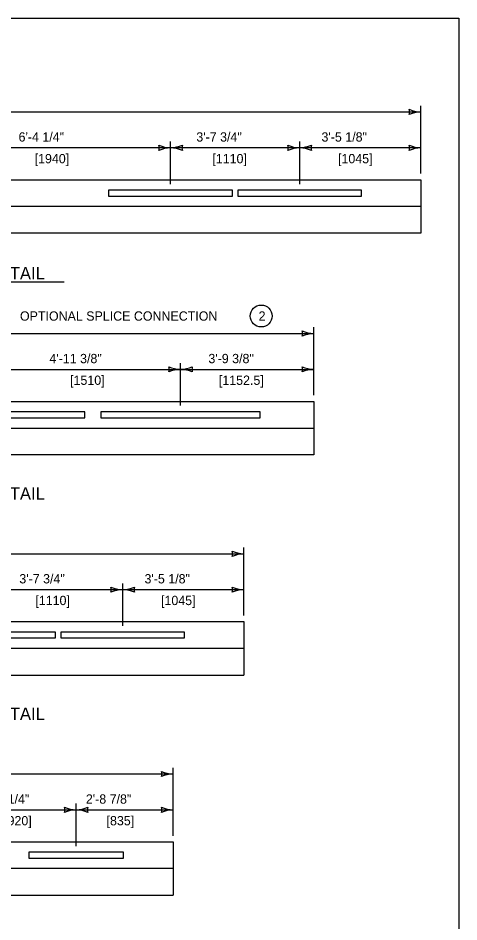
# Model space of a CAD drawing. Extents: x 49991.4 to 50021, y 49987.6 to 50011.4.
# Drawn here: x 50013.9 to 50016.75, y 49993.16 to 49999 of the extents above; entities that cross this region are included whole.
import ezdxf

# ---------------------------------------------------------------- set-up
doc = ezdxf.new("R2010")
doc.units = 0
for name, color, linetype in [('Level 1', 7, 'Continuous'), ('Level 2', 7, 'Continuous'), ('Level 3', 7, 'Continuous'), ('Level 5', 7, 'Continuous')]:
    doc.layers.add(name, color=color, linetype=linetype)

msp = doc.modelspace()

# ---------------------------------------------------------------- linework, layer by layer
at = {"layer": 'Level 1'}
for p, q in [((50009.5326, 49997.9545), (50016.5051, 49997.9545)), ((50016.5051, 49997.9545), (50016.5051, 49997.6095)), ((50015.2883, 49997.8874), (50014.4882, 49997.8874)), ((50014.4882, 49997.8874), (50014.4882, 49997.8491)), ((50014.4882, 49997.8491), (50015.2883, 49997.8491)), ((50015.2883, 49997.8491), (50015.2883, 49997.8874)), ((50016.1217, 49997.8874), (50015.3216, 49997.8874)), ((50015.3216, 49997.8874), (50015.3216, 49997.8491)), ((50015.3216, 49997.8491), (50016.1217, 49997.8491)), ((50016.1217, 49997.8491), (50016.1217, 49997.8874)), ((50016.5051, 49997.782), (50013.0188, 49997.782)), ((50016.5051, 49997.6095), (50009.5326, 49997.6095)), ((50010.2124, 49996.5232), (50015.8133, 49996.5232)), ((50015.8133, 49996.5232), (50015.8133, 49996.1782)), ((50014.3336, 49996.4561), (50013.3061, 49996.4561)), ((50014.3336, 49996.4178), (50014.3336, 49996.4561)), ((50015.4661, 49996.4561), (50014.4386, 49996.4561)), ((50014.4386, 49996.4561), (50014.4386, 49996.4178)), ((50015.4661, 49996.4178), (50015.4661, 49996.4561)), ((50013.3061, 49996.4178), (50014.3336, 49996.4178)), ((50014.4386, 49996.4178), (50015.4661, 49996.4178)), ((50010.2124, 49996.3507), (50015.8133, 49996.3507)), ((50015.8133, 49996.1782), (50010.2124, 49996.1782)), ((50010.6756, 49995.1007), (50015.3621, 49995.1007)), ((50015.3621, 49995.1007), (50015.3621, 49994.7557)), ((50014.1453, 49995.0336), (50013.3452, 49995.0336)), ((50013.3452, 49994.9953), (50014.1453, 49994.9953)), ((50014.1453, 49994.9953), (50014.1453, 49995.0336)), ((50014.9787, 49995.0336), (50014.1786, 49995.0336)), ((50014.1786, 49995.0336), (50014.1786, 49994.9953)), ((50014.1786, 49994.9953), (50014.9787, 49994.9953)), ((50014.9787, 49994.9953), (50014.9787, 49995.0336)), ((50015.3621, 49994.9282), (50010.6756, 49994.9282)), ((50010.6756, 49994.7557), (50015.3621, 49994.7557)), ((50011.1328, 49993.6782), (50014.9049, 49993.6782)), ((50014.9049, 49993.6782), (50014.9049, 49993.3332)), ((50014.5834, 49993.611), (50013.9738, 49993.611)), ((50013.9738, 49993.611), (50013.9738, 49993.5729)), ((50014.5834, 49993.5729), (50014.5834, 49993.611)), ((50013.9738, 49993.5729), (50014.5834, 49993.5729)), ((50014.9049, 49993.5057), (50011.1328, 49993.5057)), ((50011.1328, 49993.3332), (50014.9049, 49993.3332))]:
    msp.add_line(p, q, dxfattribs=at)
msp.add_lwpolyline([(49999.3835, 49998.9992), (50016.7501, 49998.9992), (50016.7501, 49987.7988), (49999.3835, 49987.7988)], close=True, dxfattribs=at)
at = {"layer": 'Level 2'}
msp.add_line((50011.8387, 49997.2947), (50014.2011, 49997.2947), dxfattribs=at)
msp.add_circle((50015.4734, 49997.0747), 0.0707, dxfattribs=at)
at = {"layer": 'Level 3'}
for p, q in [((50016.5051, 49997.9945), (50016.5051, 49998.433)), ((50011.3412, 49998.393), (50016.5051, 49998.393)), ((50014.8882, 49998.1614), (50013.4262, 49998.1614)), ((50015.7217, 49998.1614), (50014.8882, 49998.1614)), ((50016.5051, 49998.1614), (50015.7217, 49998.1614)), ((50015.8133, 49996.5632), (50015.8133, 49997.0017)), ((50013.6885, 49996.9617), (50015.8133, 49996.9617)), ((50013.8199, 49996.7301), (50014.9524, 49996.7301)), ((50014.9524, 49996.7301), (50015.8133, 49996.7301)), ((50015.3621, 49995.1407), (50015.3621, 49995.5792)), ((50010.6756, 49995.5392), (50015.3621, 49995.5392)), ((50013.7452, 49995.3076), (50014.5787, 49995.3076)), ((50014.5787, 49995.3076), (50015.3621, 49995.3076)), ((50011.1328, 49994.1167), (50014.9049, 49994.1167)), ((50014.9049, 49993.7182), (50014.9049, 49994.1567)), ((50013.5875, 49993.885), (50014.2786, 49993.885)), ((50014.2786, 49993.885), (50014.9049, 49993.885))]:
    msp.add_line(p, q, dxfattribs=at)
for centre, radius, start, end in [((50016.5142, 49998.6151), 0.2223, 247.45601, 267.63952), ((50016.3768, 49998.393), 0.0548, 342.13882, 17.86118), ((50016.5166, 49998.1602), 0.233, 92.82731, 112.07716), ((50014.8974, 49998.3835), 0.2223, 247.45601, 267.63952), ((50014.76, 49998.1614), 0.0548, 342.13882, 17.86118), ((50014.8997, 49997.9287), 0.233, 92.82731, 112.07716), ((50014.8768, 49998.3941), 0.233, 272.82731, 292.07716), ((50014.8791, 49997.9393), 0.2223, 67.45601, 87.63952), ((50015.0165, 49998.1614), 0.0548, 162.13882, 197.86118), ((50015.7308, 49998.3835), 0.2223, 247.45601, 267.63952), ((50015.5934, 49998.1614), 0.0548, 342.13882, 17.86118), ((50015.7332, 49997.9287), 0.233, 92.82731, 112.07716), ((50015.7102, 49998.3941), 0.233, 272.82731, 292.07716), ((50015.7125, 49997.9393), 0.2223, 67.45601, 87.63952), ((50015.8499, 49998.1614), 0.0548, 162.13882, 197.86118), ((50016.5142, 49998.3835), 0.2223, 247.45601, 267.63952), ((50016.3768, 49998.1614), 0.0548, 342.13882, 17.86118), ((50016.5166, 49997.9287), 0.233, 92.82731, 112.07716), ((50015.8224, 49997.1838), 0.2223, 247.45601, 267.63952), ((50015.685, 49996.9617), 0.0548, 342.13882, 17.86118), ((50015.8248, 49996.7289), 0.233, 92.82731, 112.07716), ((50014.9615, 49996.9522), 0.2223, 247.45601, 267.63952), ((50014.8242, 49996.7301), 0.0548, 342.13882, 17.86118), ((50014.9639, 49996.4974), 0.233, 92.82731, 112.07716), ((50014.9409, 49996.9628), 0.233, 272.82731, 292.07716), ((50014.9432, 49996.508), 0.2223, 67.45601, 87.63952), ((50015.0806, 49996.7301), 0.0548, 162.13882, 197.86118), ((50015.8224, 49996.9522), 0.2223, 247.45601, 267.63952), ((50015.685, 49996.7301), 0.0548, 342.13882, 17.86118), ((50015.8248, 49996.4974), 0.233, 92.82731, 112.07716), ((50015.3712, 49995.7613), 0.2223, 247.45601, 267.63952), ((50015.2338, 49995.5392), 0.0548, 342.13882, 17.86118), ((50015.3736, 49995.3064), 0.233, 92.82731, 112.07716), ((50014.5878, 49995.5297), 0.2223, 247.45601, 267.63952), ((50014.4504, 49995.3076), 0.0548, 342.13882, 17.86118), ((50014.5902, 49995.0749), 0.233, 92.82731, 112.07716), ((50014.5672, 49995.5403), 0.233, 272.82731, 292.07716), ((50014.5695, 49995.0855), 0.2223, 67.45601, 87.63952), ((50014.7069, 49995.3076), 0.0548, 162.13882, 197.86118), ((50015.3712, 49995.5297), 0.2223, 247.45601, 267.63952), ((50015.2338, 49995.3076), 0.0548, 342.13882, 17.86118), ((50015.3736, 49995.0749), 0.233, 92.82731, 112.07716), ((50014.914, 49994.3388), 0.2223, 247.45601, 267.63952), ((50014.7766, 49994.1167), 0.0548, 342.13882, 17.86118), ((50014.9164, 49993.8839), 0.233, 92.82731, 112.07716), ((50014.2878, 49994.1072), 0.2223, 247.45601, 267.63952), ((50014.1504, 49993.885), 0.0548, 342.13882, 17.86118), ((50014.2901, 49993.6523), 0.233, 92.82731, 112.07716), ((50014.2671, 49994.1177), 0.233, 272.82731, 292.07716), ((50014.2695, 49993.6629), 0.2223, 67.45601, 87.63952), ((50014.4068, 49993.885), 0.0548, 162.13882, 197.86118), ((50014.914, 49994.1072), 0.2223, 247.45601, 267.63952), ((50014.7766, 49993.885), 0.0548, 342.13882, 17.86118), ((50014.9164, 49993.6523), 0.233, 92.82731, 112.07716)]:
    msp.add_arc(centre, radius, start, end, dxfattribs=at)
at = {"layer": 'Level 5'}
for p, q in [((50014.8882, 49997.9274), (50014.8882, 49998.2014)), ((50015.7217, 49997.9274), (50015.7217, 49998.2014)), ((50014.9524, 49996.4961), (50014.9524, 49996.7701)), ((50014.5787, 49995.0736), (50014.5787, 49995.3476)), ((50014.2786, 49993.651), (50014.2786, 49993.925))]:
    msp.add_line(p, q, dxfattribs=at)

# ---------------------------------------------------------------- texts
at = {"layer": 'Level 2'}
for s, height, p in [('6\'-4 1/4"', 0.06, (50013.9066, 49998.2014)), ('3\'-7 3/4"', 0.06, (50015.0543, 49998.2014)), ('3\'-5 1/8"', 0.06, (50015.8627, 49998.2014)), ('[1940]', 0.06, (50014.0102, 49998.0614)), ('[1110]', 0.06, (50015.1579, 49998.0614)), ('[1045]', 0.06, (50015.9693, 49998.0614)), ("30' [9.0 m] CATTLE GUARD END SUPPORT DETAIL", 0.08, (50011.5172, 49997.3107)), ('OPTIONAL SPLICE CONNECTION', 0.06, (50013.9154, 49997.0447)), ('2', 0.06, (50015.4564, 49997.0447)), ('4\'-11 3/8"', 0.06, (50014.1055, 49996.7701)), ('3\'-9 3/8"', 0.06, (50015.1322, 49996.7701)), ('[1510]', 0.06, (50014.2391, 49996.6301)), ('[1152.5]', 0.06, (50015.2, 49996.6301)), ("24' [7.2 m] CATTLE GUARD END SUPPORT DETAIL", 0.08, (50011.5172, 49995.8882)), ('3\'-7 3/4"', 0.06, (50013.9113, 49995.3476)), ('3\'-5 1/8"', 0.06, (50014.7197, 49995.3476)), ('[1110]', 0.06, (50014.0149, 49995.2076)), ('[1045]', 0.06, (50014.8263, 49995.2076)), ("20' [6.0 m] CATTLE GUARD END SUPPORT DETAIL", 0.08, (50011.5172, 49994.4657)), ('3\'-0 1/4"', 0.06, (50013.6824, 49993.925)), ('2\'-8 7/8"', 0.06, (50014.3411, 49993.925)), ('[920]', 0.06, (50013.813, 49993.785)), ('[835]', 0.06, (50014.4746, 49993.785))]:
    msp.add_text(s, height=height, dxfattribs=at).set_placement(p)

doc.saveas('drawing.dxf')
